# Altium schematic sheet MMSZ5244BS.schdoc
size 127 x 101 mm
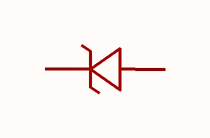
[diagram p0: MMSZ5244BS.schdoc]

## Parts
D?  mmsz5244bs  [SOD-323_L1.7-W1.3-LS2.6-RD-1]  (value not drawn)

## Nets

Not connected (* = marked no-connect by the designer): D? 1(K) 2(A)

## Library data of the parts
D? = mmsz5244bs: 二极管配置:1个独立式;稳压值(标称值):14V;稳压值(范围):13.3V~14.7V;耗散功率(Pd):200mW;; Manufacturer: CJ(江苏长电/长晶); AddInBom: yes; ModelId: eba151483b2844ffacda3a6d97308fa1; ModelTransform: 100.394,49.2125,0,0,0,0,0,0,0; Diode Configuration: 1个独立式; Zener Voltage(Nom): 14V; Reverse Leakage Current (Ir): 100nA; Pd - Power Dissipation: 200mW; Impedance(Zzt): 15Ω; Impedance(Zzk): 600Ω; Operating Junction Temperature Range: -55℃~+150℃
